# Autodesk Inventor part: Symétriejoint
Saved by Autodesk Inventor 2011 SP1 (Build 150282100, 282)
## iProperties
Created: 2010-12
Part Number: Symétriejoint
Document SubType Name: Modeling
Designer: eric
Density: 1 g/cm^3
Author: eric
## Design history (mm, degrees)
feature "Base1"
node "Solide1"
node "Corps solides"
node "Corps surfaciques"
